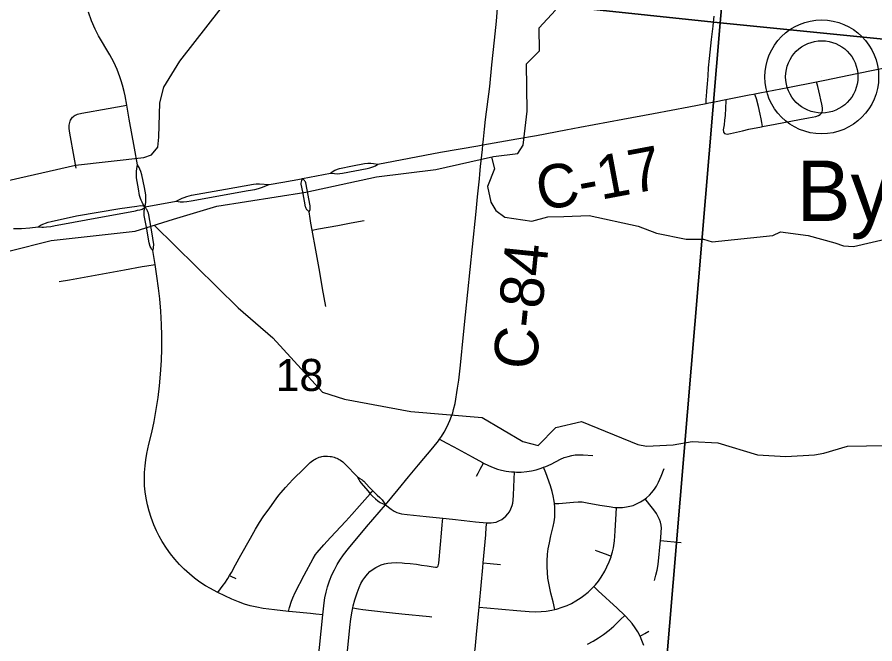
# Model space of a CAD drawing. Extents: x 0 to 34, y 0 to 22.
# Drawn here: x 27.031 to 28.153, y 14.618 to 15.436 of the extents above; entities that cross this region are included whole.
import ezdxf

# ---------------------------------------------------------------- set-up
doc = ezdxf.new("R2010")
doc.units = 0
for name, color, linetype in [('GM_X_City_Street', 7, 'Continuous'), ('GM_X_County_Road', 7, 'Continuous'), ('GM_X_County_Road_Text', 7, 'Continuous'), ('GM_X_Minor_River', 7, 'Continuous'), ('GM_X_Section', 7, 'Continuous'), ('GM_X_Section_Text', 7, 'Continuous'), ('GM_X_Township_Road', 7, 'Continuous'), ('GM_X_Unincorporated', 7, 'Continuous'), ('GM_X_Unincorporated_Location', 7, 'Continuous'), ('GM_X_Unincorporated_Text', 7, 'Continuous')]:
    doc.layers.add(name, color=color, linetype=linetype)

msp = doc.modelspace()

# ---------------------------------------------------------------- linework, layer by layer
at = {"layer": 'GM_X_City_Street'}
for points in [[(27.1888, 15.2433), (27.185, 15.2651), (27.1781, 15.303), (27.175, 15.3214), (27.1728, 15.3336), (27.1715, 15.3393), (27.1693, 15.3474), (27.1675, 15.3533), (27.1658, 15.3586), (27.1622, 15.3679), (27.1578, 15.3775), (27.1525, 15.3873), (27.1378, 15.4119), (27.1334, 15.4207), (27.1288, 15.4316), (27.1248, 15.4428)], [(27.1085, 15.239), (27.106, 15.2536), (27.1002, 15.2848), (27.0994, 15.2909), (27.0994, 15.2928), (27.0994, 15.2953), (27.0997, 15.2972), (27.1001, 15.2989), (27.1006, 15.3005), (27.1012, 15.3018), (27.102, 15.3031), (27.1028, 15.3044), (27.1038, 15.3056), (27.1049, 15.3067), (27.1061, 15.3075), (27.1075, 15.3084), (27.1086, 15.309), (27.1103, 15.3097), (27.1158, 15.3109), (27.1506, 15.317), (27.175, 15.3214)], [(27.2087, 15.1315), (27.2073, 15.1334), (27.2061, 15.1353), (27.2054, 15.137), (27.2041, 15.1417), (27.2004, 15.162), (27.1976, 15.1775), (27.1973, 15.1797), (27.1973, 15.1814), (27.1973, 15.1824), (27.1975, 15.1838), (27.1978, 15.1852), (27.1981, 15.1865), (27.1986, 15.1885), (27.197, 15.1907), (27.1959, 15.1925), (27.1948, 15.1949), (27.1936, 15.1973), (27.1927, 15.1994), (27.1915, 15.2036), (27.1901, 15.2123), (27.1876, 15.2263), (27.1873, 15.2314), (27.1873, 15.2347), (27.1878, 15.2388), (27.1888, 15.2433)], [(27.2087, 15.1315), (27.2097, 15.1347), (27.2099, 15.1365), (27.21, 15.1384), (27.21, 15.1399), (27.2099, 15.1419), (27.208, 15.1535), (27.2037, 15.1784), (27.203, 15.1804), (27.2024, 15.1821), (27.2017, 15.1835), (27.201, 15.185), (27.2003, 15.1862), (27.1986, 15.1885), (27.1993, 15.1923), (27.1995, 15.1944), (27.1996, 15.1971), (27.1996, 15.1994), (27.1997, 15.202), (27.1996, 15.2043), (27.1979, 15.2137), (27.1946, 15.2304), (27.1933, 15.2348), (27.192, 15.2378), (27.191, 15.2399), (27.1888, 15.2433)], [(27.4134, 15.1819), (27.4124, 15.1828), (27.4111, 15.1841), (27.4103, 15.1849), (27.4096, 15.1858), (27.4092, 15.1866), (27.4087, 15.1876), (27.4083, 15.1888), (27.4048, 15.2084), (27.403, 15.2182), (27.4029, 15.2197), (27.4031, 15.2211), (27.4036, 15.2231), (27.4044, 15.2256)], [(27.4134, 15.1819), (27.414, 15.184), (27.4144, 15.1852), (27.4146, 15.1866), (27.4146, 15.1877), (27.4145, 15.1888), (27.4144, 15.19), (27.409, 15.2198), (27.4083, 15.2213), (27.4077, 15.2223), (27.407, 15.2231), (27.4044, 15.2256)], [(27.4349, 15.0585), (27.4308, 15.0818), (27.4271, 15.1033), (27.422, 15.1321), (27.4172, 15.1583), (27.4156, 15.1673), (27.4146, 15.1736), (27.4134, 15.1819)], [(27.4172, 15.1583), (27.4255, 15.1598), (27.4507, 15.1644), (27.4681, 15.1676), (27.4851, 15.1708)], [(27.4312, 14.6557), (27.4219, 14.6567), (27.4151, 14.6574), (27.3916, 14.6596), (27.3862, 14.6602), (27.3681, 14.6621), (27.3533, 14.664), (27.3447, 14.6655), (27.3362, 14.6675), (27.3289, 14.6697), (27.3208, 14.6726), (27.3122, 14.6763), (27.294, 14.6849), (27.2931, 14.6854), (27.2842, 14.6899), (27.2777, 14.6937), (27.2704, 14.6985), (27.2634, 14.7036), (27.2566, 14.7092), (27.2497, 14.7154), (27.2435, 14.7216), (27.2376, 14.7282), (27.2318, 14.7355), (27.2267, 14.7426), (27.221, 14.7516), (27.217, 14.7586), (27.2136, 14.7654), (27.2102, 14.7734), (27.2067, 14.7828), (27.2041, 14.7911), (27.2019, 14.7996), (27.2001, 14.8081), (27.1989, 14.8162), (27.1981, 14.8243), (27.1979, 14.8324), (27.198, 14.8418), (27.1987, 14.8505), (27.1996, 14.858), (27.2011, 14.8666), (27.2038, 14.8787), (27.2074, 14.8939), (27.2105, 14.9084), (27.2133, 14.9237), (27.2157, 14.9396), (27.2176, 14.955), (27.2189, 14.9699), (27.22, 14.9878), (27.2206, 15.0033), (27.2207, 15.0207), (27.2203, 15.035), (27.2194, 15.0523), (27.2181, 15.0684), (27.2164, 15.0825), (27.2142, 15.0979), (27.2117, 15.1133), (27.2087, 15.1315)], [(27.0865, 15.0909), (27.0999, 15.0934), (27.1716, 15.1063), (27.1949, 15.1105), (27.201, 15.1115), (27.2117, 15.1133)], [(27.5836, 14.885), (27.5924, 14.8805), (27.6024, 14.8753), (27.6264, 14.8622), (27.6399, 14.8545), (27.6411, 14.8539), (27.6476, 14.8507), (27.6538, 14.848), (27.6596, 14.846), (27.6649, 14.8445), (27.671, 14.8433), (27.6777, 14.8425), (27.6819, 14.8423), (27.6844, 14.8422), (27.6906, 14.8422), (27.698, 14.8428), (27.704, 14.8437), (27.71, 14.8451), (27.7165, 14.8471), (27.7197, 14.8484), (27.7228, 14.8496), (27.7295, 14.8527), (27.7417, 14.859), (27.7469, 14.8612), (27.7517, 14.8627), (27.7566, 14.8639), (27.761, 14.8645), (27.766, 14.8648), (27.7717, 14.8647), (27.784, 14.8639)], [(27.3092, 14.7071), (27.3115, 14.7108), (27.317, 14.7212), (27.3239, 14.7337), (27.3364, 14.7559), (27.3432, 14.7678), (27.3483, 14.7763), (27.3531, 14.7835), (27.3618, 14.7956), (27.3702, 14.8072), (27.3738, 14.8122), (27.3765, 14.8156), (27.3823, 14.822), (27.392, 14.8324), (27.4065, 14.847), (27.4127, 14.853), (27.4145, 14.8546), (27.4164, 14.8562), (27.4194, 14.8583), (27.421, 14.8591), (27.4226, 14.86), (27.4248, 14.8609), (27.4265, 14.8615), (27.4283, 14.862), (27.43, 14.8624), (27.4321, 14.8628), (27.4336, 14.8629), (27.4354, 14.8631), (27.4372, 14.863), (27.4408, 14.8627), (27.4425, 14.8624), (27.4444, 14.862), (27.446, 14.8615), (27.4478, 14.8609), (27.4495, 14.8602), (27.4512, 14.8594), (27.4526, 14.8586), (27.4543, 14.8576), (27.4572, 14.8555), (27.4604, 14.8526), (27.4763, 14.836)], [(27.6322, 14.8369), (27.6342, 14.8406), (27.637, 14.846), (27.6411, 14.8539)], [(27.5131, 14.7992), (27.5206, 14.7936), (27.5244, 14.7911), (27.5278, 14.7894), (27.5308, 14.7883), (27.5339, 14.7876), (27.5413, 14.7867), (27.5661, 14.7842), (27.5879, 14.7819), (27.6006, 14.7805), (27.616, 14.7789), (27.6308, 14.7773), (27.6454, 14.7759), (27.6475, 14.7757), (27.6513, 14.7757), (27.6545, 14.7761), (27.6577, 14.7769), (27.6612, 14.7783), (27.6651, 14.7804), (27.6678, 14.7822), (27.6706, 14.7847), (27.6732, 14.7876), (27.675, 14.7902), (27.6771, 14.7942), (27.6788, 14.7983), (27.6796, 14.8014), (27.6802, 14.8056), (27.6805, 14.812), (27.6814, 14.8331), (27.6819, 14.8423)], [(27.7345, 14.6628), (27.7321, 14.6725), (27.7292, 14.684), (27.7269, 14.6949), (27.7255, 14.7035), (27.7247, 14.7109), (27.7243, 14.7184), (27.7244, 14.7258), (27.725, 14.7351), (27.7258, 14.7419), (27.7273, 14.7498), (27.7294, 14.7589), (27.7324, 14.7709), (27.7336, 14.777), (27.7343, 14.7832), (27.7346, 14.79), (27.7344, 14.7962), (27.7339, 14.801), (27.7335, 14.8043), (27.7324, 14.811), (27.731, 14.817), (27.7288, 14.8242), (27.7225, 14.841), (27.7197, 14.8484)], [(27.7339, 14.801), (27.7386, 14.8013), (27.7398, 14.8013), (27.759, 14.803), (27.7652, 14.8033), (27.7701, 14.8031), (27.7768, 14.8022), (27.7933, 14.7991), (27.8056, 14.797), (27.813, 14.796), (27.8149, 14.7959), (27.8181, 14.7957), (27.8231, 14.796), (27.8282, 14.7966), (27.8325, 14.7975), (27.8368, 14.7987), (27.8414, 14.8006), (27.8465, 14.8031), (27.8509, 14.8058), (27.8526, 14.8071), (27.8544, 14.8085), (27.8581, 14.8119), (27.8615, 14.8157), (27.8646, 14.8197), (27.8673, 14.8239), (27.8699, 14.829), (27.8735, 14.837), (27.8773, 14.8469)], [(27.4763, 14.836), (27.4794, 14.834), (27.4824, 14.8322), (27.4836, 14.8312), (27.4847, 14.8303), (27.4918, 14.8226), (27.4965, 14.8176)], [(27.4763, 14.836), (27.4773, 14.8337), (27.478, 14.8323), (27.4796, 14.8299), (27.4813, 14.8276), (27.4898, 14.8177), (27.4932, 14.8139)], [(27.4932, 14.8139), (27.4952, 14.8162), (27.4965, 14.8176)], [(27.4965, 14.8176), (27.4993, 14.8149), (27.5021, 14.8122), (27.5056, 14.809), (27.5071, 14.8075), (27.5087, 14.8057), (27.5105, 14.8033), (27.5131, 14.7992)], [(27.3862, 14.6602), (27.3877, 14.6654), (27.39, 14.6734), (27.3918, 14.678), (27.3949, 14.6847), (27.4067, 14.7073), (27.4184, 14.7291), (27.4215, 14.7344), (27.4237, 14.7373), (27.4323, 14.7471), (27.4411, 14.7567), (27.4611, 14.7779), (27.4691, 14.7866), (27.4789, 14.7979), (27.4932, 14.8139)], [(27.4932, 14.8139), (27.496, 14.8109), (27.5001, 14.8071), (27.5032, 14.8044), (27.5046, 14.8035), (27.5061, 14.8026), (27.5092, 14.801), (27.5131, 14.7992)], [(27.865, 14.7006), (27.8667, 14.7073), (27.8682, 14.714), (27.8694, 14.7214), (27.8727, 14.753), (27.873, 14.7559), (27.8737, 14.764), (27.8738, 14.7691), (27.8734, 14.7729), (27.8725, 14.7766), (27.8713, 14.7802), (27.8697, 14.7837), (27.8672, 14.7881), (27.864, 14.7927), (27.8586, 14.7996), (27.8526, 14.8071)], [(27.6354, 14.6657), (27.6454, 14.6648), (27.685, 14.6612), (27.7011, 14.6601), (27.7091, 14.6598), (27.7165, 14.66), (27.7231, 14.6606), (27.7305, 14.6619), (27.7345, 14.6628), (27.7366, 14.6633), (27.7442, 14.6656), (27.7505, 14.668), (27.7561, 14.6707), (27.762, 14.674), (27.7688, 14.6782), (27.7723, 14.6808), (27.7781, 14.6854), (27.7821, 14.6891), (27.7853, 14.6926), (27.7875, 14.6951), (27.7914, 14.6998), (27.7949, 14.7049), (27.7997, 14.7128), (27.8026, 14.7182), (27.8056, 14.7249), (27.808, 14.7313), (27.8083, 14.7325), (27.8099, 14.7378), (27.811, 14.7432), (27.8124, 14.7524), (27.813, 14.7583), (27.8135, 14.7653), (27.8145, 14.7876), (27.8149, 14.7959)], [(27.463, 14.604), (27.4665, 14.6393), (27.4678, 14.6504), (27.4694, 14.6603), (27.4703, 14.6649), (27.4709, 14.6676), (27.473, 14.6754), (27.4759, 14.6843), (27.4786, 14.6914), (27.4809, 14.6965), (27.4834, 14.7009), (27.486, 14.7045), (27.4896, 14.7089), (27.4927, 14.7121), (27.4957, 14.7145), (27.5004, 14.7176), (27.5038, 14.7194), (27.5073, 14.7209), (27.5116, 14.7222), (27.5159, 14.723), (27.5209, 14.7236), (27.5278, 14.7239), (27.5347, 14.7236), (27.5379, 14.7234), (27.5453, 14.7227), (27.5535, 14.7217), (27.56, 14.7207), (27.5676, 14.7195), (27.5755, 14.7182), (27.5784, 14.718), (27.5801, 14.7181), (27.581, 14.7185), (27.5817, 14.719), (27.5821, 14.7198), (27.5827, 14.7233), (27.5848, 14.7474), (27.5862, 14.7622), (27.5871, 14.7734), (27.5879, 14.7819)], [(27.6225, 14.5232), (27.6232, 14.5311), (27.6269, 14.5732), (27.6275, 14.5797), (27.63, 14.6083), (27.6303, 14.611), (27.632, 14.63), (27.6354, 14.6657), (27.6359, 14.6704), (27.6403, 14.7174), (27.6409, 14.7237), (27.6441, 14.7601), (27.6449, 14.77), (27.6454, 14.7759)], [(27.8727, 14.753), (27.8813, 14.7521), (27.8997, 14.7502)], [(27.7871, 14.74), (27.7894, 14.7391), (27.8003, 14.7353), (27.8083, 14.7325)], [(27.6409, 14.7237), (27.65, 14.7228), (27.6636, 14.7215)], [(27.294, 14.6849), (27.301, 14.6945), (27.3028, 14.697), (27.3069, 14.7033), (27.3092, 14.7071)], [(27.3092, 14.7071), (27.3109, 14.7063), (27.3175, 14.7032)], [(27.8507, 14.6155), (27.8484, 14.622), (27.8459, 14.6277), (27.8429, 14.6333), (27.8396, 14.6386), (27.8355, 14.6442), (27.8319, 14.6485), (27.8259, 14.6549), (27.8254, 14.6553), (27.8161, 14.6645), (27.7912, 14.6871), (27.7853, 14.6926)], [(27.4703, 14.6649), (27.4779, 14.6636), (27.4834, 14.6627), (27.5099, 14.6596), (27.5346, 14.6571), (27.5705, 14.6534), (27.5735, 14.6531)], [(27.7773, 14.6176), (27.7845, 14.6213), (27.7914, 14.6255), (27.798, 14.63), (27.8054, 14.6357), (27.8116, 14.641), (27.8205, 14.6496), (27.8259, 14.6549)], [(27.8459, 14.6277), (27.852, 14.6312), (27.8575, 14.6344)]]:
    msp.add_lwpolyline(points, dxfattribs=at)
at = {"layer": 'GM_X_County_Road'}
for p, q in [((27.9432, 15.3259), (27.958, 15.3289)), ((27.4044, 15.2256), (27.4411, 15.2325)), ((27.1986, 15.1885), (27.2395, 15.196)), ((27.4226, 14.5738), (27.4312, 14.6557))]:
    msp.add_line(p, q, dxfattribs=at)
for points in [[(27.6405, 15.2696), (27.6413, 15.2772), (27.6426, 15.2902), (27.6439, 15.3026), (27.6493, 15.3457), (27.6523, 15.3741), (27.6556, 15.4062), (27.658, 15.431), (27.6594, 15.4483), (27.6597, 15.4527)], [(28.0767, 15.3518), (28.0874, 15.354), (28.1294, 15.3626), (28.1763, 15.3722), (28.2177, 15.3802), (28.3007, 15.3959), (28.3605, 15.4073), (28.411, 15.4176), (28.456, 15.4272)], [(27.996, 15.3363), (28.0027, 15.3376), (28.0393, 15.3444), (28.0767, 15.3518)], [(27.958, 15.3289), (27.9887, 15.335), (27.9942, 15.336), (27.996, 15.3363)], [(27.6405, 15.2696), (27.6849, 15.2773), (27.7105, 15.2819), (27.7489, 15.2891), (27.7673, 15.2925), (27.8234, 15.3031), (27.8637, 15.3107), (27.9095, 15.3193), (27.9325, 15.3238)], [(27.9325, 15.3238), (27.9357, 15.3244), (27.9432, 15.3259)], [(27.5032, 15.2444), (27.585, 15.2599), (27.6339, 15.2685), (27.6405, 15.2696)], [(27.6041, 14.9319), (27.6074, 14.9517), (27.6089, 14.9621), (27.6111, 14.9818), (27.6151, 15.022), (27.6176, 15.0474), (27.6267, 15.1364), (27.6317, 15.1827), (27.6335, 15.2018), (27.6358, 15.2253), (27.6365, 15.2315), (27.6375, 15.2414), (27.6399, 15.2636), (27.6405, 15.2696)], [(27.4411, 15.2325), (27.4433, 15.2342), (27.447, 15.2366), (27.4531, 15.2389), (27.47, 15.2422), (27.4858, 15.2451), (27.4901, 15.2456), (27.4937, 15.2456), (27.4974, 15.2453), (27.5032, 15.2444)], [(27.4411, 15.2325), (27.4463, 15.232), (27.4497, 15.2319), (27.4532, 15.2321), (27.4569, 15.2325), (27.4892, 15.2388), (27.4926, 15.2396), (27.4966, 15.2409), (27.4999, 15.2424), (27.5032, 15.2444)], [(27.2395, 15.196), (27.2439, 15.1983), (27.2472, 15.1999), (27.2498, 15.201), (27.2533, 15.2023), (27.2564, 15.203), (27.2593, 15.2037), (27.3039, 15.2119), (27.3403, 15.2183), (27.3441, 15.2187), (27.3481, 15.2188), (27.361, 15.218)], [(27.361, 15.218), (27.379, 15.221), (27.4034, 15.2254), (27.4044, 15.2256)], [(27.2395, 15.196), (27.2445, 15.1953), (27.2468, 15.1952), (27.2491, 15.1953), (27.2535, 15.1957), (27.2591, 15.1964), (27.3334, 15.2098), (27.3424, 15.2114), (27.347, 15.2126), (27.351, 15.2139), (27.361, 15.218)], [(27.0587, 15.1627), (27.0627, 15.165), (27.0718, 15.1685), (27.076, 15.1695), (27.109, 15.1768), (27.1659, 15.1864), (27.188, 15.1896), (27.1928, 15.1902), (27.1963, 15.1898), (27.1986, 15.1885)], [(27.0836, 15.1647), (27.1429, 15.1757), (27.184, 15.1831), (27.1862, 15.1835), (27.189, 15.1842), (27.1918, 15.1848), (27.1934, 15.1853), (27.1949, 15.1858), (27.196, 15.1863), (27.197, 15.1868), (27.1979, 15.1875), (27.1986, 15.1885)], [(27.0268, 15.1603), (27.0371, 15.1605), (27.0478, 15.1614), (27.0587, 15.1627)], [(27.0587, 15.1627), (27.0612, 15.1624), (27.0636, 15.1621), (27.0658, 15.162), (27.0699, 15.1624), (27.0753, 15.1631), (27.0811, 15.1643), (27.0836, 15.1647)], [(27.5836, 14.885), (27.5862, 14.8886), (27.5897, 14.8944), (27.5935, 14.9015), (27.5972, 14.9094), (27.5995, 14.9152), (27.6009, 14.9196), (27.6021, 14.9237), (27.6041, 14.9319)], [(27.5131, 14.7992), (27.5295, 14.8196), (27.543, 14.8358), (27.5561, 14.8515), (27.5749, 14.8738), (27.5822, 14.883), (27.5836, 14.885)], [(27.4312, 14.6557), (27.4316, 14.6597), (27.4329, 14.6715), (27.4339, 14.6777), (27.4355, 14.6851), (27.4374, 14.6924), (27.44, 14.7002), (27.443, 14.7078), (27.4462, 14.7146), (27.4499, 14.7213), (27.4535, 14.7272), (27.4582, 14.7339), (27.4648, 14.7423), (27.4883, 14.7705), (27.5131, 14.7992)]]:
    msp.add_lwpolyline(points, dxfattribs=at)
at = {"layer": 'GM_X_Minor_River'}
for points in [[(27.0101, 15.2207), (27.1078, 15.2432), (27.1969, 15.2531), (27.2072, 15.2567), (27.2154, 15.2664), (27.2168, 15.2796), (27.218, 15.3243), (27.2234, 15.3451), (27.2441, 15.3791), (27.298, 15.4482), (27.3687, 15.5585), (27.4314, 15.6308), (27.4418, 15.6405), (27.4478, 15.6528), (27.4568, 15.6879), (27.4663, 15.8091), (27.467, 15.8216), (27.4701, 15.9049), (27.4668, 15.9498), (27.4673, 15.9529)], [(27.0204, 15.1309), (27.076, 15.1445), (27.1856, 15.157), (27.2359, 15.1727), (27.2926, 15.1897), (27.4088, 15.2078), (27.5011, 15.2278), (27.5789, 15.2372), (27.6545, 15.2542), (27.686, 15.2581), (27.6931, 15.2694), (27.6985, 15.3136), (27.6974, 15.3754), (27.7144, 15.3925), (27.7138, 15.4225), (27.7355, 15.4456)], [(27.6515, 15.2536), (27.6554, 15.2383), (27.6466, 15.215), (27.6507, 15.1948), (27.6573, 15.1837), (27.6689, 15.1751), (27.7043, 15.1698), (27.7253, 15.1754), (27.7461, 15.1761), (27.7794, 15.1774), (27.8435, 15.1635), (27.8675, 15.1543), (27.9064, 15.1463), (27.9287, 15.1462), (27.9404, 15.1429), (28.0196, 15.1512), (28.0296, 15.1559), (28.0658, 15.151), (28.1008, 15.1415), (28.1121, 15.1379), (28.1249, 15.1368), (28.204, 15.1549)], [(27.2108, 15.1649), (27.3203, 15.0568), (27.3657, 15.0176), (27.4309, 14.9465), (27.4595, 14.9375), (27.5462, 14.9213), (27.6395, 14.9133), (27.6927, 14.8823), (27.7126, 14.8769), (27.7358, 14.9004), (27.7692, 14.9084), (27.8428, 14.8784), (27.8545, 14.8759), (27.8894, 14.8778), (27.9141, 14.8823), (27.9477, 14.8804), (27.9996, 14.8646), (28.0367, 14.8627), (28.0742, 14.8649), (28.086, 14.8669), (28.1172, 14.8762), (28.1668, 14.8767)]]:
    msp.add_lwpolyline(points, dxfattribs=at)
at = {"layer": 'GM_X_Section'}
for points in [[(27.036, 16.5489), (28.0435, 16.442), (27.9506, 15.429), (26.9382, 15.5362)], [(29.042, 16.3387), (28.9498, 15.3294), (27.9506, 15.429), (28.0435, 16.442)], [(26.9382, 15.5362), (27.9506, 15.429), (27.8702, 14.4696), (26.8568, 14.5735)], [(27.9506, 15.429), (28.9498, 15.3294), (28.8697, 14.3676), (27.8702, 14.4696)]]:
    msp.add_lwpolyline(points, close=True, dxfattribs=at)
at = {"layer": 'GM_X_Township_Road'}
for points in [[(27.9325, 15.3238), (27.9325, 15.3268), (27.9325, 15.3292), (27.9327, 15.3329), (27.9332, 15.3399), (27.934, 15.3492), (27.9349, 15.3597), (27.9356, 15.3702), (27.9367, 15.3826), (27.9394, 15.4072), (27.9413, 15.4245), (27.9422, 15.4338), (27.9426, 15.4375)], [(28.0062, 15.2934), (28.0224, 15.2966), (28.0546, 15.3029), (28.0661, 15.3049), (28.0759, 15.3068), (28.0794, 15.3079), (28.0816, 15.3091), (28.0833, 15.3109), (28.0841, 15.3125), (28.0845, 15.3149), (28.0843, 15.318), (28.0835, 15.3229), (28.0823, 15.3283), (28.081, 15.3343), (28.0782, 15.3459), (28.0767, 15.3518)], [(28.0062, 15.2934), (28.0052, 15.2986), (28.0041, 15.3038), (28.0028, 15.3098), (28.0008, 15.3196), (27.998, 15.3298), (27.9966, 15.3344), (27.996, 15.3363)], [(27.958, 15.3289), (27.958, 15.3273), (27.9577, 15.3174), (27.9571, 15.3081), (27.9565, 15.302), (27.9557, 15.2958), (27.9548, 15.289), (27.9549, 15.2871), (27.9552, 15.286), (27.9563, 15.2845), (27.9579, 15.2839), (27.9598, 15.2837), (27.9641, 15.2845), (27.9798, 15.2881), (27.9883, 15.29), (28.0047, 15.2931), (28.0062, 15.2934)]]:
    msp.add_lwpolyline(points, dxfattribs=at)
at = {"layer": 'GM_X_Unincorporated'}
for radius in [0.0744, 0.0472]:
    msp.add_circle((28.0835, 15.3584), radius, dxfattribs=at)
at = {"layer": 'GM_X_Unincorporated_Location'}
msp.add_line((28.0835, 15.3584), (28.0835, 15.3584), dxfattribs=at)

# ---------------------------------------------------------------- texts
at = {"layer": 'GM_X_County_Road_Text'}
for s, rotation, p in [('C-17', 10.6392, (27.7158, 15.183)), ('C-84', 84.1878, (27.7098, 14.9744))]:
    msp.add_text(s, height=0.05682, rotation=rotation, dxfattribs=at).set_placement(p)
at = {"layer": 'GM_X_Section_Text'}
msp.add_text('18', height=0.04186, rotation=0, dxfattribs=at).set_placement((27.3694, 14.9481))
at = {"layer": 'GM_X_Unincorporated_Text'}
msp.add_text('Byron', height=0.07898, rotation=0, dxfattribs=at).set_placement((28.0507, 15.1701))

doc.saveas('drawing.dxf')
